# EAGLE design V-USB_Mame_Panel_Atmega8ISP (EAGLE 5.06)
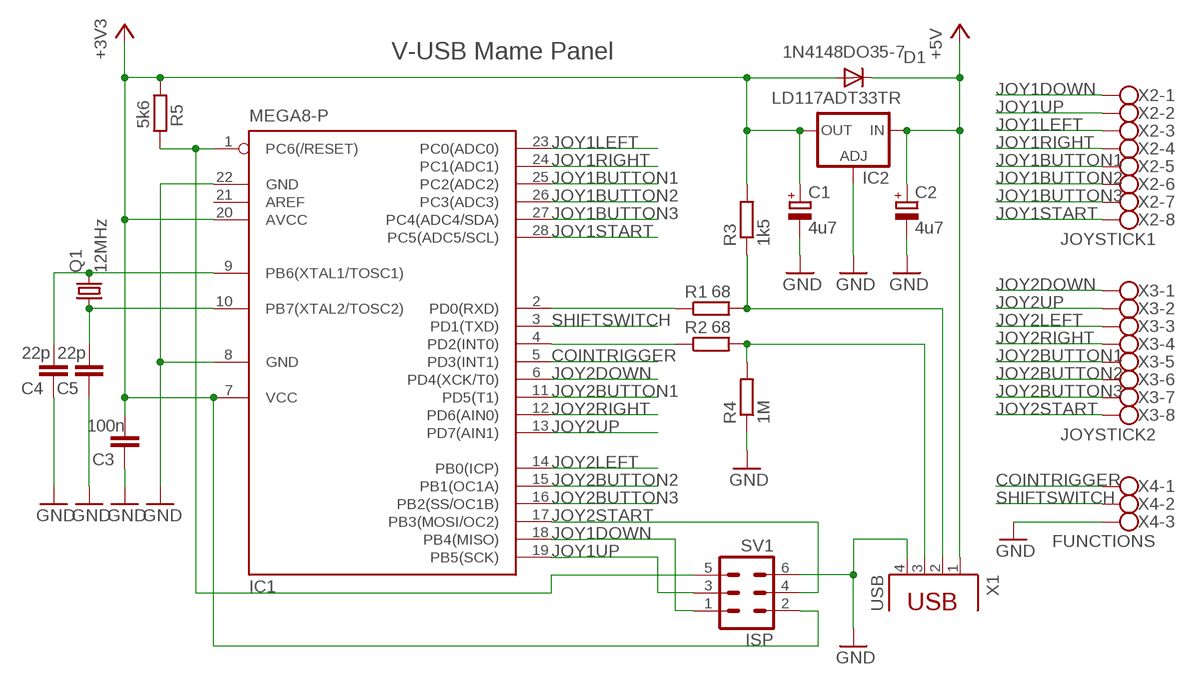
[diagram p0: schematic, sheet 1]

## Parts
C1  4u7  CPOL-EUE2.5-5  [E2,5-5]
C2  4u7  CPOL-EUE2.5-5  [E2,5-5]
C3  100n  C-EU050-030X075  [C050-030X075]
C4  22p  C-EU025-025X050  [C025-025X050]
C5  22p  C-EU025-025X050  [C025-025X050]
D1  1N4148DO35-7  [DO35-7]
IC1  MEGA8-P  [DIL28-3]
IC2  LD117ADT33TR  [DPACK]
Q1  12MHz  CRYSTALHC18U-V  [HC18U-V]
R1  68  R-EU_0207/10  [0207/10]
R2  68  R-EU_0207/12  [0207/12]
R3  1k5  R-EU_0207/10  [0207/10]
R4  1M  R-EU_0207/10  [0207/10]
R5  5k6  R-EU_0207/10  [0207/10]
SV1  ISP  ML6  [ML6]
X1  USB  PN61729  [PN61729]
X2  JOYSTICK1  W237-08P  [W237-8P]
X3  JOYSTICK2  W237-08P  [W237-8P]
X4  FUNCTIONS  W237-03P  [W237-133]

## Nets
+3V3: C1.+ C3.2 D1.A IC1.7(VCC) IC1.20(AVCC) IC2.4(OUT) R3.2 R5.1 SV1.2
+5V: C2.+ D1.C IC2.3(IN) X1.1
COINTRIGGER: IC1.5(PD3(INT1)) X4.1
GND: C1.- C2.- C3.1 C4.1 C5.1 IC1.8(GND) IC1.22(GND) IC2.1(ADJ) R4.1 SV1.6 X1.4 X4.3
JOY1BUTTON1: IC1.25(PC2(ADC2)) X2.5
JOY1BUTTON2: IC1.26(PC3(ADC3)) X2.6
JOY1BUTTON3: IC1.27(PC4(ADC4/SDA)) X2.7
JOY1DOWN: IC1.18(PB4(MISO)) SV1.1 X2.1
JOY1LEFT: IC1.23(PC0(ADC0)) X2.3
JOY1RIGHT: IC1.24(PC1(ADC1)) X2.4
JOY1START: IC1.28(PC5(ADC5/SCL)) X2.8
JOY1UP: IC1.19(PB5(SCK)) SV1.3 X2.2
JOY2BUTTON1: IC1.11(PD5(T1)) X3.5
JOY2BUTTON2: IC1.15(PB1(OC1A)) X3.6
JOY2BUTTON3: IC1.16(PB2(SS/OC1B)) X3.7
JOY2DOWN: IC1.6(PD4(XCK/T0)) X3.1
JOY2LEFT: IC1.14(PB0(ICP)) X3.3
JOY2RIGHT: IC1.12(PD6(AIN0)) X3.4
JOY2START: IC1.17(PB3(MOSI/OC2)) SV1.4 X3.8
JOY2UP: IC1.13(PD7(AIN1)) X3.2
N$1: IC1.2(PD0(RXD)) R1.1
N$2: IC1.4(PD2(INT0)) R2.1
N$3: IC1.1(PC6(/RESET)) R5.2 SV1.5
N$4: R1.2 R3.1 X1.2
N$5: R2.2 R4.2 X1.3
N$10: C4.2 IC1.9(PB6(XTAL1/TOSC1)) Q1.2
N$11: C5.2 IC1.10(PB7(XTAL2/TOSC2)) Q1.1
SHIFTSWITCH: IC1.3(PD1(TXD)) X4.2
Unconnected: IC1.21(AREF)

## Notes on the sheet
- V-USB Mame Panel

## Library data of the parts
C1 C2 = rcl:CPOL-EU: POLARIZED CAPACITOR, European symbol
C3-C5 = resistor:C-EU: CAPACITOR, European symbol
D1 = diode:1N4148: DIODE
IC1 = atmel:MEGA8-P: MICROCONTROLLER 8 Kbytes FLASH, 1 kbytes SRAM, 512 bytes EEPROM, USART, 4-channel 10 bit ADC, 2-channel 8 bit ADC Pin compatible with Atmega48, ATMega88, ATMega168 Source: avr.lbr
IC2 = v-reg:LD117A?*: Low drop fixed and adjustable positive voltage regulators 1 A Source: http://www.st.com/stonline/products/literature/ds/7194/ld1117axx.pdf
Q1 = crystal:CRYSTAL: CRYSTAL
R1-R5 = resistor:R-EU_: RESISTOR, European symbol
SV1 = con-harting-ml:ML6: HARTING
X1 = con-berg:PN61729: BERG USB connector
X2 X3 = con-wago-508:W237-08P: WAGO SREW CLAMP
X4 = con-wago-508:W237-03P: WAGO SREW CLAMP

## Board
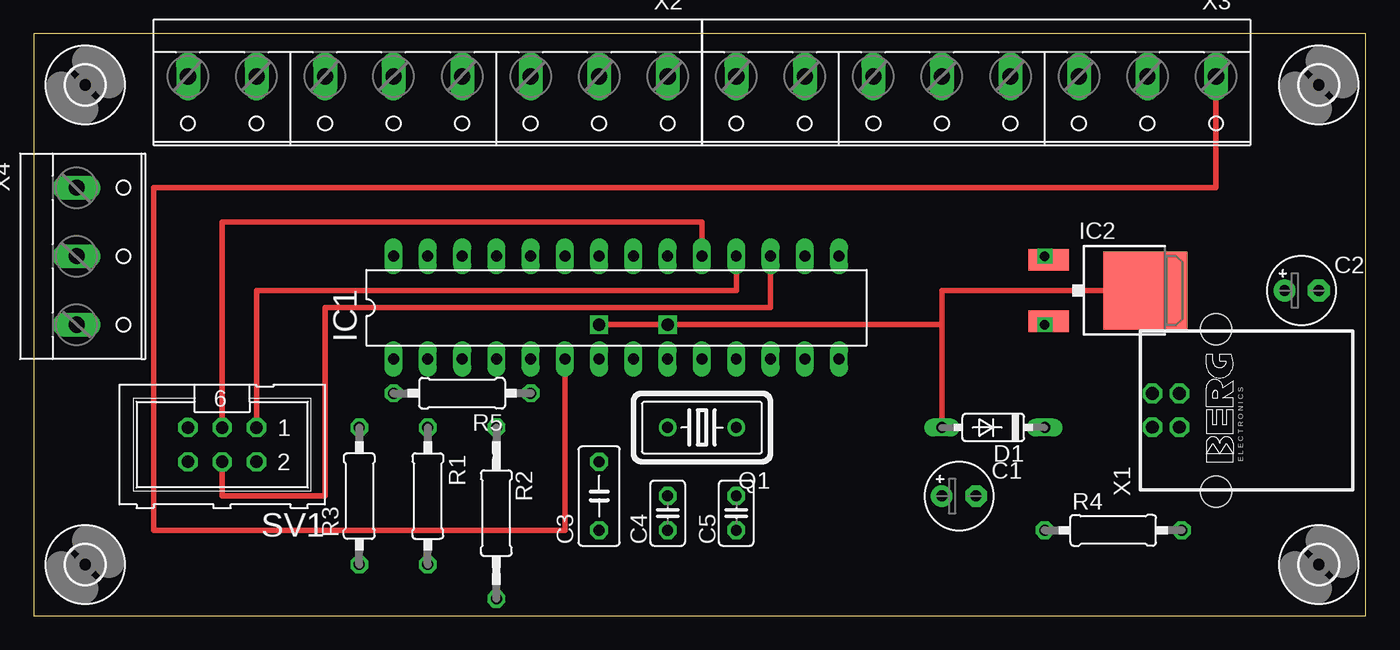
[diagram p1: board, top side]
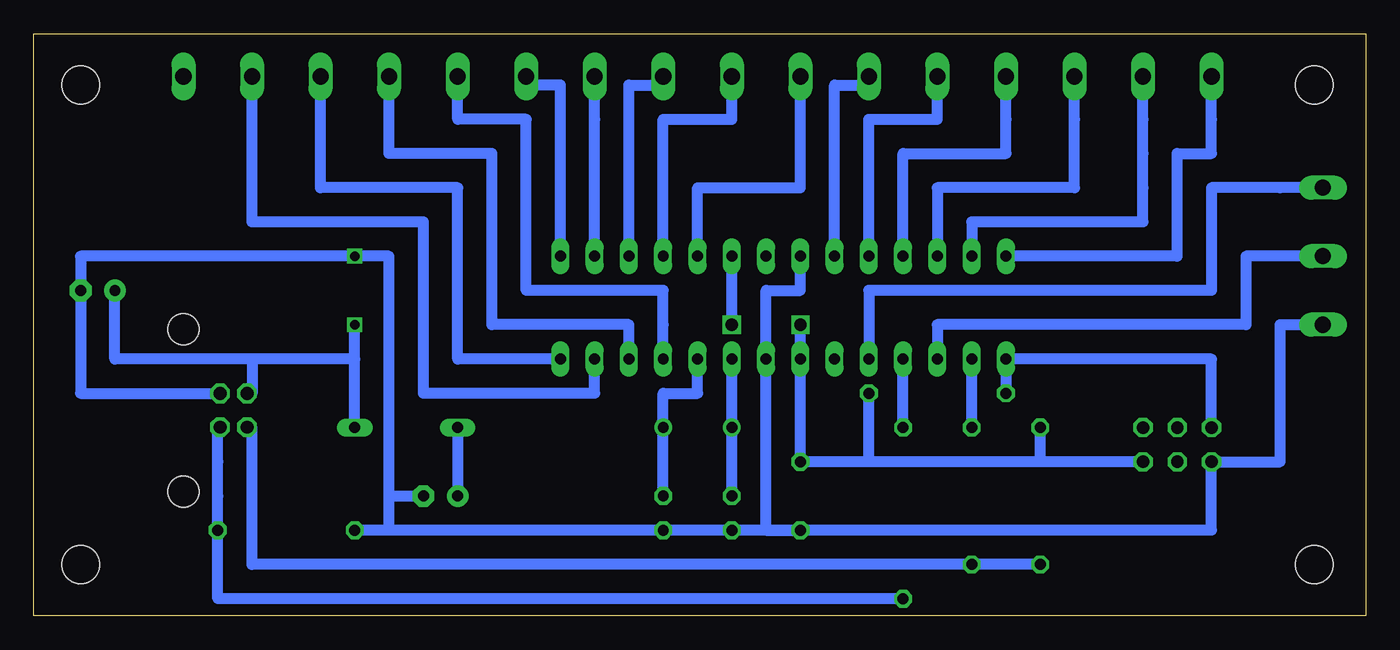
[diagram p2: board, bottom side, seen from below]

Size 98.73 x 43.17 mm. Coordinates in mm from the lower left corner, seen from the top.
Outline: 0,0 98.73,0 98.73,43.17 0,43.17 0,0
Copper layers (1*16): Top 0.035mm / dielectric 1.5mm / Bottom 0.035mm
Design rules "default": minimum track width 10mil, minimum drill 24mil, track to track 8mil, track to pad 8mil, pad to pad 8mil, via to via 8mil, smd to smd 8mil, copper to edge 40mil, drill to drill 8mil, minimum pad ring 10mil, minimum via ring 8mil, stop-mask expansion 4mil, vias tented up to drill 0mil, thermal gap 10mil

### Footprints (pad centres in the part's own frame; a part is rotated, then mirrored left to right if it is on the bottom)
E2,5-5 = drill 0.813 pad 1.6 round: + -1.27,0 | drill 0.813 pad 1.6 octagon: - 1.27,0
C050-030X075 = drill 0.813 octagon: 1 -2.54,0; 2 2.54,0
C025-025X050 = drill 0.813 octagon: 1 -1.27,0; 2 1.27,0
DO35-7 = drill 0.813 long: A 3.81,0; C -3.81,0
DIL28-3 = drill 0.813 long: 1 -16.51,-3.81; 2 -13.97,-3.81; 3 -11.43,-3.81; 4 -8.89,-3.81; 5 -6.35,-3.81; 6 -3.81,-3.81; 7 -1.27,-3.81; 8 1.27,-3.81; 9 3.81,-3.81; 10 6.35,-3.81; 11 8.89,-3.81; 12 11.43,-3.81; 13 13.97,-3.81; 14 16.51,-3.81; 15 16.51,3.81; 16 13.97,3.81; 17 11.43,3.81; 18 8.89,3.81; 19 6.35,3.81; 20 3.81,3.81; 21 1.27,3.81; 22 -1.27,3.81; 23 -3.81,3.81; 24 -6.35,3.81; 25 -8.89,3.81; 26 -11.43,3.81; 27 -13.97,3.81; 28 -16.51,3.81
DPACK = smd 1.6 x 3: 1 -2.28,-4.8; 3 2.28,-4.8 | smd 5.8 x 6.2: 4 0,2.38
HC18U-V = drill 0.813 round: 1 -2.54,0; 2 2.54,0
0207/10 = drill 0.813 octagon: 1 -5.08,0; 2 5.08,0
0207/12 = drill 0.813 octagon: 1 -6.35,0; 2 6.35,0
ML6 = drill 0.914 octagon: 1 -2.54,-1.27; 2 -2.54,1.27; 3 0,-1.27; 4 0,1.27; 5 2.54,-1.27; 6 2.54,1.27
2,8 = hole 2.8: 0,0
PN61729 = drill 0.95 octagon: 1 1.25,4.71; 2 -1.25,4.71; 3 -1.25,2.71; 4 1.25,2.71 | hole 2.3: -6.02,0; 6.02,0
W237-8P = drill 1.194 long: 1 -17.78,-0.635; 2 -12.7,-0.635; 3 -7.62,-0.635; 4 -2.54,-0.635; 5 2.54,-0.635; 6 7.62,-0.635; 7 12.7,-0.635; 8 17.78,-0.635
W237-133 = drill 1.194 long: 1 -5.08,-0.635; 2 0,-0.635; 3 5.08,-0.635

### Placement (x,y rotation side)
C1  68.58,8.89 0 top
C2  93.98,24.13 0 top
C3  41.91,8.89 90 top
C4  46.99,7.62 90 top
C5  52.07,7.62 90 top
D1  71.12,13.97 180 top
IC1  43.18,22.86 0 top
IC2  80.01,24.13 270 top
Q1  49.53,13.97 180 top
R1  29.21,8.89 270 top
R2  34.29,7.62 270 top
R3  24.13,8.89 90 top
R4  80.01,6.35 0 top
R5  31.75,16.51 180 top
SV1  13.97,12.7 180 top
U$1  [2,8]  3.81,39.37 0 top
U$2  [2,8]  3.81,3.81 0 top
U$3  [2,8]  95.25,3.81 0 top
U$4  [2,8]  95.25,39.37 0 top
X1  87.63,15.24 90 top
X2  29.21,39.37 180 top
X3  69.85,39.37 180 top
X4  3.81,26.67 270 top

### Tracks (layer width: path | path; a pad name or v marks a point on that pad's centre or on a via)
+3V3  (via drill 0.9)
  Top 0.406: v41.91,21.59 v46.99,21.59 67.31,21.59 | IC2.4 67.31,24.13 67.31,21.59 | 67.31,21.59 D1.A
  Bottom 0.813: 24.13,11.43 36.83,11.43 | SV1.2 24.13,11.43 | 24.13,11.43 R3.2 | v46.99,21.59 IC1.20 | 36.83,11.43 R5.1 | 36.83,11.43 C3.2 IC1.7 | IC1.7 v41.91,21.59 IC1.7 | D1.A C1.+
+5V  (via drill 0.7)
  Top 0.813: IC2.3 74.93,21.85 v74.93,21.59
  Bottom 0.813: X1.1 82.55,16.49 82.55,19.05 | 74.93,19.05 v74.93,21.59 | 74.93,19.05 82.55,19.05 | D1.C 74.93,19.05 | 82.55,19.05 92.71,19.05 C2.+
COINTRIGGER
  Bottom 0.813: X4.1 6.35,31.75 11.43,31.75 11.43,24.13 24.13,24.13 36.83,24.13 IC1.5
GND  (via drill 0.7)
  Top 0.813: IC2.1 74.93,26.41 v74.93,26.67
  Bottom 0.813: 44.45,6.35 C4.1 C5.1 72.39,6.35 | IC1.22 41.91,24.13 44.45,24.13 IC1.8 44.45,6.35 | 44.45,6.35 C3.1 | X4.3 6.35,21.59 6.35,11.43 SV1.6 11.43,6.35 44.45,6.35 | 72.39,6.35 R4.1 | 72.39,11.43 72.39,16.51 | 72.39,11.43 72.39,26.67 v74.93,26.67 95.25,26.67 C2.- 95.25,16.51 84.92,16.51 X1.4 | 72.39,8.89 72.39,11.43 | 72.39,8.89 C1.- | 72.39,6.35 72.39,8.89
JOY1BUTTON1
  Bottom 0.813: IC1.25 34.29,34.29 26.67,34.29 26.67,36.83 X2.5
JOY1BUTTON2
  Bottom 0.813: IC1.26 31.75,31.75 21.59,31.75 21.59,36.83 X2.6
JOY1BUTTON3
  Bottom 0.813: IC1.27 29.21,29.21 19.05,29.21 16.51,29.21 16.51,31.75 16.51,34.29 16.51,36.83 X2.7
JOY1DOWN
  Top 0.406: SV1.1 16.51,24.13 52.07,24.13 IC1.18
  Bottom 0.813: IC1.18 52.07,36.83 46.99,36.83 X2.1
JOY1LEFT
  Bottom 0.813: IC1.23 39.37,39.37 36.83,39.37 X2.3
JOY1RIGHT
  Bottom 0.813: IC1.24 36.83,36.83 31.75,36.83 X2.4
JOY1START
  Bottom 0.813: IC1.28 13.97,26.67 13.97,31.75 13.97,34.29 11.43,34.29 11.43,36.83 11.43,39.37 X2.8
JOY1UP
  Top 0.406: SV1.3 13.97,29.21 49.53,29.21 IC1.19
  Bottom 0.813: IC1.19 49.53,31.75 41.91,31.75 41.91,36.83 X2.2
JOY2BUTTON1
  Bottom 0.813: IC1.11 52.07,21.59 52.07,24.13 54.61,24.13 62.23,24.13 62.23,36.83 67.31,36.83 X3.5
JOY2BUTTON2
  Bottom 0.813: IC1.15 59.69,39.37 62.23,39.37 X3.6
JOY2BUTTON3
  Bottom 0.813: X3.7 57.15,39.37 57.15,36.83 IC1.16
JOY2DOWN
  Top 0.406: IC1.6 39.37,6.35 8.89,6.35 8.89,31.75 87.63,31.75 X3.1
JOY2LEFT
  Bottom 0.813: IC1.14 67.31,19.05 67.31,31.75 77.47,31.75 X3.3
JOY2RIGHT
  Bottom 0.813: IC1.12 54.61,21.59 64.77,21.59 64.77,34.29 72.39,34.29 72.39,36.83 X3.4
JOY2START
  Top 0.406: SV1.4 13.97,8.89 21.59,8.89 21.59,22.86 54.61,22.86 IC1.17
  Bottom 0.813: IC1.17 54.61,39.37 52.07,39.37 X3.8
JOY2UP
  Bottom 0.813: 69.85,29.21 72.39,29.21 | 69.85,29.21 82.55,29.21 X3.2 | 69.85,29.21 69.85,16.51 57.15,16.51 IC1.13
N$1
  Bottom 0.813: R1.1 IC1.2
N$2
  Bottom 0.813: R2.1 IC1.4
N$3
  Bottom 0.406: IC1.1 R5.2
  Bottom 0.813: SV1.5 11.43,19.05 IC1.1 | IC1.1 R5.2 IC1.1
N$4
  Bottom 0.813: R3.1 R1.2 82.55,3.81 82.55,13.97 82.92,13.97 X1.2
N$5
  Bottom 0.813: R2.2 85.09,1.27 R4.2 85.09,8.89 85.09,11.43 85.09,13.97 84.92,13.97 X1.3
N$10
  Bottom 0.813: C4.2 Q1.2 IC1.9
N$11
  Bottom 0.813: IC1.10 49.53,16.51 52.07,16.51 Q1.1 C5.2
SHIFTSWITCH
  Bottom 0.813: X4.2 8.89,26.67 8.89,21.59 31.75,21.59 IC1.3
